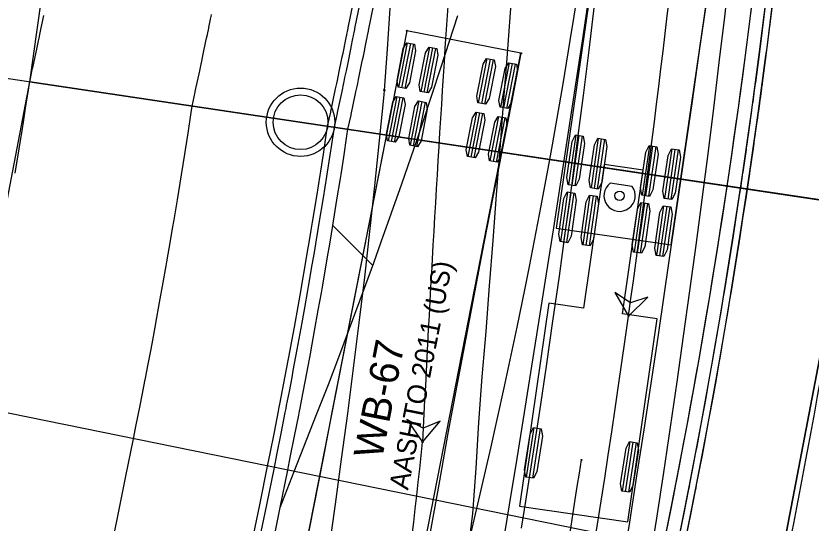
# Model space of a CAD drawing. Extents: x -70 to 701944, y -4 to 666871.
# Drawn here: x 664327.1 to 664385.1, y 657010.2 to 657047.3 of the extents above; entities that cross this region are included whole.
import ezdxf

# ---------------------------------------------------------------- set-up
doc = ezdxf.new("R2010")
doc.units = 0
for name, color, linetype in [('R_Detour', 7, 'Continuous'), ('R_Horz Alg', 7, 'Continuous'), ('R_Horz Alg Annot', 7, 'Continuous'), ('R_No Plot', 7, 'Continuous'), ('R_Proposed Road', 7, 'Continuous'), ('R_Striping', 7, 'Continuous'), ('R_Water', 7, 'Continuous'), ('T_Vehicle Path Lt Major', 7, 'Continuous'), ('T_Vehicle Path Lt Minor', 7, 'Continuous'), ('T_Vehicle Path Rt', 7, 'Continuous')]:
    doc.layers.add(name, color=color, linetype=linetype)

msp = doc.modelspace()

# ---------------------------------------------------------------- linework, layer by layer
at = {"layer": 'R_Detour'}
msp.add_line((664261.474, 657052.457), (664387.896, 657033.536), dxfattribs=at)
at = {"layer": 'R_Horz Alg'}
msp.add_lwpolyline([(664382.951, 657034.276), (664387.896, 657033.536)], dxfattribs=at)
msp.add_arc((663872.762, 657110.632), 520.871, 348.49417, 356.81395, dxfattribs=at)
at = {"layer": 'R_Horz Alg Annot'}
msp.add_lwpolyline([(664383.166, 657006.736), (664237.632, 657036.36)], dxfattribs=at)
at = {"layer": 'R_No Plot'}
for points in [[(664328.065, 657042.491), (664341.279, 657136.216), (664395.695, 657133.187), (664392.683, 657079.188), (664387.896, 657033.536)], [(664309.134, 656943.398), (664328.069, 657042.49), (664387.896, 657033.536), (664369.102, 656935.334)], [(664369.102, 656935.334), (664387.896, 657033.536), (664436.522, 657026.259), (664427.617, 656981.959), (664423.421, 656948.669), (664424.449, 656927.891)]]:
    msp.add_lwpolyline(points, close=True, dxfattribs=at)
msp.add_circle((664347.842, 657039.531), 2.5, dxfattribs=at)
msp.add_arc((663872.762, 657110.633), 511.871, 348.49414, 356.81396, dxfattribs=at)
at = {"layer": 'R_Proposed Road'}
for points in [[(664368.47, 656979.661), (664369.039, 656982.456), (664369.608, 656985.253), (664369.802, 656986.207), (664370.178, 656988.051), (664370.747, 656990.85), (664371.797, 656996.006), (664373.792, 657005.805), (664374.347, 657008.531), (664375.253, 657013.087), (664375.713, 657015.491), (664376.117, 657017.651), (664376.94, 657022.223), (664377.447, 657025.164), (664377.722, 657026.803), (664378.462, 657031.389), (664378.995, 657034.868), (664379.16, 657035.981), (664379.817, 657040.58), (664380.356, 657044.601), (664380.432, 657045.185), (664381.005, 657049.795)], [(664369.442, 656979.461), (664370.011, 656982.256), (664370.581, 656985.053), (664370.775, 656986.007), (664371.15, 656987.851), (664371.72, 656990.65), (664372.77, 656995.806), (664374.764, 657005.605), (664375.32, 657008.334), (664376.227, 657012.896), (664376.689, 657015.305), (664377.093, 657017.471), (664377.918, 657022.05), (664378.426, 657024.996), (664378.701, 657026.64), (664379.442, 657031.234), (664379.976, 657034.719), (664380.142, 657035.837), (664380.8, 657040.443), (664381.34, 657044.47), (664381.416, 657045.059), (664381.99, 657049.676)], [(664369.929, 656979.361), (664370.498, 656982.156), (664371.067, 656984.953), (664371.261, 656985.907), (664371.637, 656987.751), (664372.206, 656990.55), (664373.256, 656995.706), (664375.251, 657005.505), (664375.806, 657008.235), (664376.714, 657012.8), (664377.176, 657015.212), (664377.582, 657017.381), (664378.407, 657021.963), (664378.915, 657024.913), (664379.191, 657026.559), (664379.933, 657031.156), (664380.467, 657034.645), (664380.634, 657035.765), (664381.292, 657040.375), (664381.832, 657044.405), (664381.909, 657044.996), (664382.483, 657049.617)], [(664374.544, 657009.505), (664374.874, 657011.156), (664375.194, 657012.786), (664375.253, 657013.087), (664375.297, 657013.315), (664375.509, 657014.42), (664375.713, 657015.491), (664375.815, 657016.031), (664376.117, 657017.651), (664376.12, 657017.666), (664376.42, 657019.304), (664376.704, 657020.886), (664376.94, 657022.223), (664376.996, 657022.543), (664377.284, 657024.207), (664377.447, 657025.164), (664377.563, 657025.849), (664377.722, 657026.803), (664377.828, 657027.444), (664378.149, 657029.416), (664378.412, 657031.068), (664378.462, 657031.389), (664378.668, 657032.716), (664378.919, 657034.36), (664378.995, 657034.868), (664379.16, 657035.981), (664379.166, 657036.017), (664379.406, 657037.671), (664379.426, 657037.806), (664379.484, 657038.213), (664379.518, 657038.449), (664379.561, 657038.75), (664379.636, 657039.281), (664379.706, 657039.784), (664379.743, 657040.047), (664379.778, 657040.299), (664379.817, 657040.58), (664379.889, 657041.102), (664379.894, 657041.142), (664379.984, 657041.799), (664380.013, 657042.016), (664380.035, 657042.179), (664380.049, 657042.281), (664380.08, 657042.515), (664380.08, 657042.516), (664380.082, 657042.527), (664380.083, 657042.536), (664380.086, 657042.554), (664380.089, 657042.576), (664380.356, 657044.601), (664380.432, 657045.185), (664381.005, 657049.795)], [(664375.524, 657009.308), (664375.855, 657010.962), (664376.176, 657012.595), (664376.234, 657012.896), (664376.278, 657013.124), (664376.492, 657014.232), (664376.696, 657015.305), (664376.798, 657015.846), (664377.101, 657017.47), (664377.103, 657017.484), (664377.404, 657019.125), (664377.688, 657020.711), (664377.925, 657022.051), (664377.981, 657022.371), (664378.27, 657024.038), (664378.433, 657024.997), (664378.549, 657025.684), (664378.708, 657026.639), (664378.815, 657027.282), (664379.136, 657029.257), (664379.399, 657030.913), (664379.45, 657031.234), (664379.656, 657032.564), (664379.907, 657034.211), (664379.984, 657034.72), (664380.149, 657035.835), (664380.155, 657035.872), (664380.396, 657037.528), (664380.416, 657037.663), (664380.474, 657038.072), (664380.508, 657038.308), (664380.551, 657038.61), (664380.626, 657039.142), (664380.697, 657039.646), (664380.733, 657039.909), (664380.768, 657040.162), (664380.807, 657040.443), (664380.879, 657040.966), (664380.885, 657041.007), (664380.975, 657041.664), (664381.004, 657041.882), (664381.026, 657042.045), (664381.04, 657042.147), (664381.071, 657042.382), (664381.072, 657042.383), (664381.073, 657042.394), (664381.074, 657042.403), (664381.077, 657042.421), (664381.08, 657042.443), (664381.348, 657044.472), (664381.423, 657045.057), (664381.998, 657049.676)], [(664376.014, 657009.209), (664376.345, 657010.865), (664376.666, 657012.5), (664376.725, 657012.801), (664376.769, 657013.029), (664376.983, 657014.138), (664377.187, 657015.212), (664377.289, 657015.754), (664377.592, 657017.379), (664377.595, 657017.393), (664377.896, 657019.036), (664378.181, 657020.623), (664378.418, 657021.964), (664378.474, 657022.285), (664378.763, 657023.954), (664378.926, 657024.913), (664379.042, 657025.601), (664379.202, 657026.557), (664379.308, 657027.2), (664379.63, 657029.178), (664379.893, 657030.835), (664379.944, 657031.156), (664380.151, 657032.488), (664380.402, 657034.136), (664380.478, 657034.646), (664380.644, 657035.763), (664380.649, 657035.799), (664380.891, 657037.457), (664380.911, 657037.592), (664380.969, 657038.001), (664381.003, 657038.237), (664381.046, 657038.54), (664381.121, 657039.072), (664381.192, 657039.576), (664381.229, 657039.84), (664381.264, 657040.093), (664381.303, 657040.375), (664381.375, 657040.898), (664381.38, 657040.939), (664381.47, 657041.597), (664381.5, 657041.815), (664381.522, 657041.978), (664381.535, 657042.081), (664381.567, 657042.315), (664381.567, 657042.316), (664381.569, 657042.328), (664381.57, 657042.337), (664381.572, 657042.354), (664381.575, 657042.377), (664381.844, 657044.407), (664381.919, 657044.993), (664382.494, 657049.616)], [(664344.265, 657008.647), (664344.885, 657011.689), (664345.439, 657014.415), (664345.625, 657015.333), (664345.936, 657016.889), (664346.238, 657018.425), (664346.293, 657018.709), (664346.335, 657018.923), (664346.535, 657019.965), (664346.727, 657020.974), (664346.823, 657021.483), (664347.108, 657023.01), (664347.11, 657023.024), (664347.393, 657024.567), (664347.661, 657026.058), (664347.884, 657027.318), (664347.936, 657027.62), (664348.208, 657029.188), (664348.361, 657030.09), (664348.47, 657030.736), (664348.62, 657031.634), (664348.72, 657032.238), (664349.022, 657034.097), (664349.27, 657035.654), (664349.318, 657035.956), (664349.512, 657037.207), (664349.748, 657038.756), (664349.82, 657039.235), (664350.044, 657040.274), (664350.051, 657040.307), (664350.379, 657041.851), (664350.405, 657041.977), (664350.485, 657042.358), (664350.531, 657042.578), (664350.59, 657042.859), (664350.693, 657043.355), (664350.79, 657043.825), (664350.841, 657044.071), (664350.89, 657044.306), (664350.943, 657044.569), (664351.043, 657045.057), (664351.051, 657045.095), (664351.175, 657045.708), (664351.216, 657045.911), (664351.247, 657046.063), (664351.266, 657046.159), (664351.31, 657046.378), (664351.31, 657046.379), (664351.312, 657046.389), (664351.314, 657046.398), (664351.317, 657046.414), (664351.322, 657046.435), (664351.698, 657048.329)], [(664344.755, 657008.547), (664345.374, 657011.589), (664345.929, 657014.315), (664346.116, 657015.235), (664346.427, 657016.792), (664346.729, 657018.33), (664346.784, 657018.613), (664346.826, 657018.828), (664347.026, 657019.871), (664347.219, 657020.881), (664347.315, 657021.391), (664347.6, 657022.919), (664347.602, 657022.933), (664347.885, 657024.478), (664348.153, 657025.971), (664348.376, 657027.232), (664348.429, 657027.534), (664348.7, 657029.103), (664348.854, 657030.006), (664348.963, 657030.653), (664349.113, 657031.552), (664349.213, 657032.157), (664349.516, 657034.017), (664349.764, 657035.576), (664349.811, 657035.878), (664350.006, 657037.131), (664350.242, 657038.681), (664350.314, 657039.161), (664350.538, 657040.201), (664350.545, 657040.234), (664350.874, 657041.78), (664350.9, 657041.906), (664350.98, 657042.287), (664351.026, 657042.507), (664351.085, 657042.789), (664351.188, 657043.285), (664351.286, 657043.756), (664351.336, 657044.002), (664351.385, 657044.238), (664351.439, 657044.501), (664351.538, 657044.989), (664351.546, 657045.027), (664351.671, 657045.641), (664351.712, 657045.844), (664351.742, 657045.997), (664351.762, 657046.092), (664351.806, 657046.311), (664351.806, 657046.312), (664351.808, 657046.323), (664351.81, 657046.332), (664351.813, 657046.347), (664351.817, 657046.369), (664352.193, 657048.264)], [(664345.735, 657008.348), (664346.354, 657011.39), (664346.909, 657014.116), (664347.096, 657015.037), (664347.408, 657016.598), (664347.71, 657018.139), (664347.766, 657018.423), (664347.807, 657018.638), (664348.009, 657019.683), (664348.201, 657020.695), (664348.298, 657021.206), (664348.583, 657022.738), (664348.586, 657022.751), (664348.869, 657024.3), (664349.138, 657025.795), (664349.361, 657027.059), (664349.414, 657027.362), (664349.686, 657028.934), (664349.84, 657029.839), (664349.949, 657030.487), (664350.1, 657031.388), (664350.2, 657031.995), (664350.503, 657033.859), (664350.752, 657035.421), (664350.799, 657035.723), (664350.994, 657036.978), (664351.231, 657038.532), (664351.303, 657039.013), (664351.528, 657040.055), (664351.535, 657040.089), (664351.863, 657041.637), (664351.89, 657041.764), (664351.97, 657042.145), (664352.016, 657042.366), (664352.075, 657042.649), (664352.179, 657043.146), (664352.276, 657043.618), (664352.327, 657043.864), (664352.375, 657044.1), (664352.429, 657044.364), (664352.529, 657044.853), (664352.537, 657044.891), (664352.662, 657045.507), (664352.703, 657045.71), (664352.733, 657045.863), (664352.753, 657045.959), (664352.797, 657046.178), (664352.797, 657046.179), (664352.799, 657046.19), (664352.801, 657046.198), (664352.804, 657046.214), (664352.808, 657046.236), (664353.185, 657048.135)], [(664327.013, 657035.814), (664327.301, 657037.587), (664327.538, 657039.074), (664327.583, 657039.361), (664327.768, 657040.556), (664327.993, 657042.034), (664328.062, 657042.491), (664328.279, 657043.482), (664328.286, 657043.514), (664328.603, 657044.987), (664328.629, 657045.107), (664328.707, 657045.47), (664328.751, 657045.68), (664328.808, 657045.949), (664328.908, 657046.422), (664329.002, 657046.87), (664329.051, 657047.105), (664329.098, 657047.329)], [(664333.091, 657003.885), (664334.466, 657010.641), (664335.085, 657013.684), (664335.64, 657016.41), (664335.823, 657017.309), (664336.127, 657018.833), (664336.423, 657020.337), (664336.476, 657020.614), (664336.517, 657020.824), (664336.714, 657021.844), (664336.902, 657022.833), (664336.996, 657023.331), (664337.274, 657024.826), (664337.277, 657024.84), (664337.553, 657026.352), (664337.816, 657027.812), (664338.034, 657029.046), (664338.086, 657029.341), (664338.351, 657030.876), (664338.502, 657031.759), (664338.608, 657032.392), (664338.755, 657033.272), (664338.853, 657033.864), (664339.149, 657035.683), (664339.392, 657037.208), (664339.438, 657037.504), (664339.628, 657038.729), (664339.859, 657040.246), (664339.93, 657040.715), (664340.15, 657041.732), (664340.158, 657041.765), (664340.481, 657043.276), (664340.507, 657043.4), (664340.586, 657043.773), (664340.631, 657043.988), (664340.689, 657044.264), (664340.791, 657044.749), (664340.887, 657045.209), (664340.937, 657045.45), (664340.984, 657045.68), (664341.037, 657045.938), (664341.136, 657046.415), (664341.143, 657046.452), (664341.266, 657047.053), (664341.306, 657047.252), (664341.337, 657047.401)]]:
    msp.add_lwpolyline(points, dxfattribs=at)
at = {"layer": 'R_Striping'}
msp.add_line((664350.195, 657031.98), (664353.115, 657029.06), dxfattribs=at)
for points in [[(664360.073, 657008.598), (664360.71, 657011.307), (664361.73, 657015.712), (664362.252, 657018.037), (664362.711, 657020.128), (664363.652, 657024.553), (664364.235, 657027.401), (664364.553, 657028.989), (664365.414, 657033.433), (664366.039, 657036.807), (664366.234, 657037.887), (664367.015, 657042.349), (664367.663, 657046.252), (664367.755, 657046.819), (664368.454, 657051.297)], [(664346.354, 657011.39), (664347.373, 657014.022), (664349.019, 657018.18), (664349.872, 657020.379), (664350.629, 657022.36), (664352.202, 657026.561), (664353.192, 657029.271), (664353.738, 657030.784), (664355.236, 657035.028), (664356.347, 657038.258), (664356.698, 657039.293), (664358.121, 657043.578), (664359.333, 657047.335)]]:
    msp.add_lwpolyline(points, dxfattribs=at)
at = {"layer": 'R_Water'}
msp.add_circle((664347.842, 657039.531), 2, dxfattribs=at)
at = {"layer": 'T_Vehicle Path Lt Major'}
for p, q in [((664355.598, 657046.205), (664345.408, 656994.193)), ((664363.94, 657044.57), (664355.598, 657046.205)), ((664355.025, 657042.088), (664355.66, 657045.326)), ((664355.25, 657042.044), (664355.885, 657045.282)), ((664355.475, 657042), (664356.11, 657045.238)), ((664356.644, 657041.771), (664357.279, 657045.009)), ((664356.869, 657041.727), (664357.504, 657044.965)), ((664353.749, 656992.559), (664363.94, 657044.57)), ((664357.094, 657041.683), (664357.729, 657044.921)), ((664360.848, 657040.947), (664361.482, 657044.186)), ((664361.073, 657040.903), (664361.707, 657044.141)), ((664361.298, 657040.859), (664361.932, 657044.097)), ((664362.467, 657040.63), (664363.102, 657043.868)), ((664362.692, 657040.586), (664363.326, 657043.824)), ((664362.917, 657040.542), (664363.551, 657043.78)), ((664354.256, 657038.163), (664354.891, 657041.401)), ((664354.481, 657038.118), (664355.116, 657041.357)), ((664354.706, 657038.074), (664355.34, 657041.313)), ((664355.875, 657037.845), (664356.51, 657041.084)), ((664356.1, 657037.801), (664356.735, 657041.04)), ((664356.325, 657037.757), (664356.96, 657040.996)), ((664360.079, 657037.022), (664360.713, 657040.26)), ((664360.304, 657036.978), (664360.938, 657040.216)), ((664360.529, 657036.934), (664361.163, 657040.172)), ((664361.698, 657036.704), (664362.333, 657039.943)), ((664361.923, 657036.66), (664362.557, 657039.899)), ((664362.148, 657036.616), (664362.782, 657039.855))]:
    msp.add_line(p, q, dxfattribs=at)
for points in [[(664370.586, 657059.335), (664370.44, 657058.012), (664370.069, 657054.704), (664369.687, 657051.398), (664369.295, 657048.093), (664368.892, 657044.79), (664368.478, 657041.488), (664368.054, 657038.187), (664367.619, 657034.888), (664367.174, 657031.59), (664366.717, 657028.294), (664366.25, 657024.999), (664365.772, 657021.707), (664365.283, 657018.42), (664364.784, 657015.135), (664364.274, 657011.851), (664363.963, 657009.882)], [(664380.036, 657058.591), (664379.897, 657057.254), (664379.54, 657053.912), (664379.171, 657050.571), (664378.79, 657047.231), (664378.397, 657043.893), (664377.992, 657040.556), (664377.575, 657037.221), (664377.146, 657033.887), (664376.706, 657030.555), (664376.255, 657027.224), (664375.792, 657023.895), (664375.317, 657020.568), (664374.832, 657017.248), (664374.335, 657013.93), (664373.827, 657010.614), (664373.516, 657008.625)], [(664355.598, 657046.205), (664354.918, 657042.737), (664354.237, 657039.27), (664353.559, 657035.803), (664352.881, 657032.335), (664352.202, 657028.867), (664351.522, 657025.4), (664350.843, 657021.933), (664350.163, 657018.465), (664349.484, 657014.998), (664348.805, 657011.53), (664348.125, 657008.063), (664347.446, 657004.596), (664346.767, 657001.128), (664346.087, 656997.661), (664345.408, 656994.193), (664345.408, 656994.193), (664344.769, 656990.837), (664344.157, 656987.475), (664343.56, 656984.111), (664342.944, 656980.75)], [(664363.94, 657044.57), (664363.26, 657041.103), (664362.581, 657037.635), (664361.904, 657034.168), (664361.23, 657030.699), (664360.562, 657027.229), (664359.902, 657023.758), (664359.251, 657020.286), (664358.61, 657016.811), (664357.981, 657013.334), (664357.366, 657009.855), (664356.765, 657006.373), (664356.18, 657002.888), (664355.611, 656999.401), (664355.059, 656995.911), (664354.521, 656992.419), (664354.013, 656989.04), (664353.516, 656985.66), (664353.029, 656982.279), (664352.551, 656978.898)]]:
    msp.add_lwpolyline(points, dxfattribs=at)
for points in [[(664355.531, 657041.989), (664354.969, 657042.099), (664354.889, 657042.585), (664355.346, 657044.917), (664355.604, 657045.337), (664356.165, 657045.227), (664356.246, 657044.741), (664355.789, 657042.409)], [(664357.15, 657041.672), (664356.589, 657041.782), (664356.508, 657042.268), (664356.965, 657044.6), (664357.223, 657045.02), (664357.785, 657044.91), (664357.865, 657044.424), (664357.408, 657042.092)], [(664361.353, 657040.848), (664360.792, 657040.958), (664360.712, 657041.445), (664361.169, 657043.776), (664361.427, 657044.196), (664361.988, 657044.086), (664362.068, 657043.6), (664361.611, 657041.268)], [(664362.973, 657040.531), (664362.411, 657040.641), (664362.331, 657041.127), (664362.788, 657043.459), (664363.046, 657043.879), (664363.607, 657043.769), (664363.687, 657043.283), (664363.231, 657040.951)], [(664354.762, 657038.063), (664354.2, 657038.173), (664354.12, 657038.66), (664354.577, 657040.992), (664354.835, 657041.412), (664355.396, 657041.302), (664355.477, 657040.815), (664355.02, 657038.484)], [(664356.381, 657037.746), (664355.82, 657037.856), (664355.739, 657038.343), (664356.196, 657040.674), (664356.454, 657041.095), (664357.015, 657040.985), (664357.096, 657040.498), (664356.639, 657038.166)], [(664360.584, 657036.923), (664360.023, 657037.033), (664359.943, 657037.519), (664360.4, 657039.851), (664360.658, 657040.271), (664361.219, 657040.161), (664361.299, 657039.675), (664360.842, 657037.343)], [(664362.204, 657036.605), (664361.642, 657036.715), (664361.562, 657037.202), (664362.019, 657039.534), (664362.277, 657039.954), (664362.838, 657039.844), (664362.918, 657039.357), (664362.462, 657037.026)], [(664371.786, 657025.356), (664373.213, 657026.757), (664371.926, 657026.347), (664370.802, 657027.098)]]:
    msp.add_lwpolyline(points, close=True, dxfattribs=at)
for centre in [(664355.598, 657046.205), (664363.94, 657044.57), (664371.786, 657025.356), (664371.786, 657025.356)]:
    msp.add_circle(centre, 0.0417, dxfattribs=at)
for centre, radius, start, end in [((663455.405, 657154.995), 925.505, 351.947905, 357.106325), ((663409.952, 657160.277), 971.25, 345.570092, 352.014984)]:
    msp.add_arc(centre, radius, start, end, dxfattribs=at)
at = {"layer": 'T_Vehicle Path Lt Minor'}
for p, q in [((664374.07, 657084.255), (664366.504, 657031.797)), ((664374.917, 657030.584), (664382.483, 657083.041)), ((664367.445, 657034.962), (664367.968, 657038.591)), ((664367.672, 657034.93), (664368.195, 657038.559)), ((664367.899, 657034.897), (664368.422, 657038.526)), ((664369.078, 657034.727), (664369.602, 657038.356)), ((664369.305, 657034.694), (664369.828, 657038.323)), ((664369.532, 657034.661), (664370.055, 657038.29)), ((664372.823, 657034.187), (664373.346, 657037.816)), ((664373.05, 657034.154), (664373.573, 657037.783)), ((664373.276, 657034.121), (664373.8, 657037.75)), ((664374.456, 657033.951), (664374.979, 657037.58)), ((664374.683, 657033.918), (664375.206, 657037.548)), ((664374.909, 657033.886), (664375.433, 657037.515)), ((664370.02, 657036.443), (664368.507, 657025.952)), ((664372.858, 657036.034), (664370.02, 657036.443)), ((664371.345, 657025.543), (664372.858, 657036.034)), ((664372.054, 657034.845), (664370.455, 657035.075)), ((664366.846, 657030.805), (664367.369, 657034.434)), ((664367.072, 657030.773), (664367.596, 657034.402)), ((664367.299, 657030.74), (664367.823, 657034.369)), ((664368.479, 657030.57), (664369.002, 657034.199)), ((664368.705, 657030.537), (664369.229, 657034.166)), ((664368.932, 657030.504), (664369.456, 657034.133)), ((664372.223, 657030.03), (664372.747, 657033.659)), ((664372.45, 657029.997), (664372.973, 657033.626)), ((664372.677, 657029.964), (664373.2, 657033.593)), ((664373.856, 657029.794), (664374.38, 657033.423)), ((664374.083, 657029.761), (664374.607, 657033.391)), ((664374.31, 657029.729), (664374.833, 657033.358)), ((664366.504, 657031.797), (664374.917, 657030.584)), ((664374.917, 657030.584), (664374.917, 657030.584)), ((664365.967, 657026.318), (664363.826, 657011.472)), ((664368.507, 657025.952), (664365.967, 657026.318)), ((664373.885, 657025.176), (664371.345, 657025.543)), ((664371.744, 657010.33), (664373.885, 657025.176)), ((664364.342, 657013.594), (664364.907, 657017.217)), ((664364.569, 657013.559), (664365.133, 657017.182)), ((664364.795, 657013.524), (664365.36, 657017.147)), ((664371.352, 657012.573), (664371.916, 657016.196)), ((664371.578, 657012.538), (664372.143, 657016.161)), ((664371.805, 657012.502), (664372.369, 657016.125)), ((664363.826, 657011.472), (664371.744, 657010.33)), ((664371.744, 657010.33), (664371.744, 657010.33))]:
    msp.add_line(p, q, dxfattribs=at)
for points in [[(664368.972, 657049.291), (664368.449, 657045.797), (664367.921, 657042.303), (664367.39, 657038.81), (664366.854, 657035.317), (664366.314, 657031.826), (664366.314, 657031.826), (664365.787, 657028.45), (664365.255, 657025.075), (664364.719, 657021.701), (664364.178, 657018.327), (664363.632, 657014.955), (664363.081, 657011.583), (664363.081, 657011.583), (664362.542, 657008.301), (664361.999, 657005.02), (664361.453, 657001.739), (664360.905, 656998.458), (664360.355, 656995.178), (664360.3, 656994.851)], [(664377.439, 657048.07), (664376.935, 657044.573), (664376.43, 657041.076), (664375.926, 657037.578), (664375.422, 657034.081), (664374.917, 657030.584), (664374.425, 657027.203), (664373.926, 657023.823), (664373.421, 657020.444), (664372.908, 657017.066), (664372.386, 657013.689), (664371.86, 657010.313), (664371.86, 657010.313), (664371.338, 657007.012), (664370.809, 657003.711), (664370.273, 657000.412), (664369.731, 656997.114), (664369.183, 656993.817), (664369.127, 656993.488)]]:
    msp.add_lwpolyline(points, dxfattribs=at)
for points in [[(664367.955, 657034.889), (664367.389, 657034.97), (664367.291, 657035.503), (664367.668, 657038.116), (664367.912, 657038.599), (664368.478, 657038.518), (664368.576, 657037.985), (664368.199, 657035.372)], [(664369.588, 657034.653), (664369.022, 657034.735), (664368.925, 657035.268), (664369.301, 657037.88), (664369.545, 657038.364), (664370.111, 657038.282), (664370.209, 657037.75), (664369.832, 657035.137)], [(664373.333, 657034.113), (664372.766, 657034.195), (664372.669, 657034.727), (664373.046, 657037.34), (664373.29, 657037.824), (664373.856, 657037.742), (664373.953, 657037.21), (664373.576, 657034.597)], [(664374.966, 657033.878), (664374.4, 657033.959), (664374.302, 657034.492), (664374.679, 657037.105), (664374.923, 657037.588), (664375.489, 657037.507), (664375.586, 657036.974), (664375.21, 657034.361)], [(664367.355, 657030.732), (664366.789, 657030.813), (664366.692, 657031.346), (664367.069, 657033.959), (664367.313, 657034.443), (664367.879, 657034.361), (664367.976, 657033.828), (664367.599, 657031.215)], [(664368.988, 657030.496), (664368.422, 657030.578), (664368.325, 657031.111), (664368.702, 657033.724), (664368.946, 657034.207), (664369.512, 657034.125), (664369.609, 657033.593), (664369.232, 657030.98)], [(664372.733, 657029.956), (664372.167, 657030.038), (664372.07, 657030.571), (664372.446, 657033.183), (664372.69, 657033.667), (664373.256, 657033.585), (664373.354, 657033.053), (664372.977, 657030.44)], [(664374.366, 657029.721), (664373.8, 657029.802), (664373.703, 657030.335), (664374.08, 657032.948), (664374.323, 657033.431), (664374.89, 657033.35), (664374.987, 657032.817), (664374.61, 657030.204)], [(664364.851, 657013.515), (664364.286, 657013.603), (664364.195, 657014.137), (664364.602, 657016.745), (664364.851, 657017.226), (664365.416, 657017.138), (664365.507, 657016.604), (664365.101, 657013.996)], [(664371.861, 657012.494), (664371.295, 657012.582), (664371.204, 657013.115), (664371.611, 657015.724), (664371.86, 657016.205), (664372.425, 657016.117), (664372.516, 657015.583), (664372.11, 657012.974)]]:
    msp.add_lwpolyline(points, close=True, dxfattribs=at)
for centre, radius in [((664371.139, 657034.16), 0.34), ((664368.356, 657014.86), 0.0417)]:
    msp.add_circle(centre, radius, dxfattribs=at)
for centre, radius, start, end in [((664371.139, 657034.16), 1.143, 126.79349, 36.79349), ((662673.915, 657278.931), 1714.894, 349.047575, 351.141971)]:
    msp.add_arc(centre, radius, start, end, dxfattribs=at)
at = {"layer": 'T_Vehicle Path Rt'}
for points in [[(664357.537, 657088.508), (664357.236, 657085.104), (664356.944, 657081.7), (664356.656, 657078.295), (664356.656, 657078.295), (664356.381, 657074.956), (664356.111, 657071.616), (664355.848, 657068.275), (664355.591, 657064.934), (664355.34, 657061.593), (664355.095, 657058.251), (664354.857, 657054.908), (664354.625, 657051.566), (664354.398, 657048.222), (664354.178, 657044.879), (664353.957, 657041.872)], [(664366.268, 657087.677), (664365.994, 657084.272), (664365.724, 657080.866), (664365.459, 657077.46), (664365.459, 657077.46), (664365.203, 657074.134), (664364.948, 657070.808), (664364.692, 657067.482), (664364.434, 657064.156), (664364.178, 657060.831), (664363.922, 657057.505), (664363.666, 657054.179), (664363.41, 657050.854), (664363.154, 657047.528), (664362.898, 657044.203), (664362.668, 657041.21)], [(664353.957, 657041.872), (664353.925, 657041.538), (664353.59, 657038.205), (664353.242, 657034.873), (664352.879, 657031.542), (664352.501, 657028.214), (664352.106, 657024.887), (664351.695, 657021.562), (664351.266, 657018.24), (664350.82, 657014.92), (664350.362, 657011.617), (664349.896, 657008.351), (664349.419, 657005.086), (664348.933, 657001.824), (664348.44, 656998.564), (664347.94, 656995.306), (664347.435, 656992.049), (664347.08, 656989.77)], [(664362.668, 657041.21), (664362.642, 657040.877), (664362.386, 657037.552), (664362.13, 657034.227), (664361.874, 657030.901), (664361.618, 657027.576), (664361.361, 657024.25), (664361.085, 657020.926), (664360.844, 657017.599), (664360.645, 657014.269), (664360.391, 657010.934), (664359.994, 657007.592), (664359.571, 657004.252), (664359.123, 657000.915), (664358.65, 656997.582), (664358.151, 656994.252), (664357.628, 656990.927), (664357.246, 656988.601)]]:
    msp.add_lwpolyline(points, dxfattribs=at)
msp.add_lwpolyline([(664356.751, 657016.169), (664358.045, 657017.694), (664356.8, 657017.168), (664355.613, 657017.813)], close=True, dxfattribs=at)
for centre in [(664353.957, 657041.872), (664353.957, 657041.872), (664362.668, 657041.21), (664362.668, 657041.21), (664356.751, 657016.169), (664356.751, 657016.169)]:
    msp.add_circle(centre, 0.0417, dxfattribs=at)
for centre, radius, start, end in [((666209.939, 656925.295), 1855.415, 175.158671, 177.192659), ((663917.805, 657061.893), 441.322, 345.91294, 354.05303)]:
    msp.add_arc(centre, radius, start, end, dxfattribs=at)

# ---------------------------------------------------------------- texts
at = {"layer": 'T_Vehicle Path Lt Major'}
for s, height, p in [('AASHTO 2011 (US)', 1.41667, (664355.693, 657012.609)), ('WB-67', 2.125, (664353.786, 657014.85))]:
    msp.add_text(s, height=height, rotation=78.91466, dxfattribs=at).set_placement(p)

doc.saveas('drawing.dxf')
